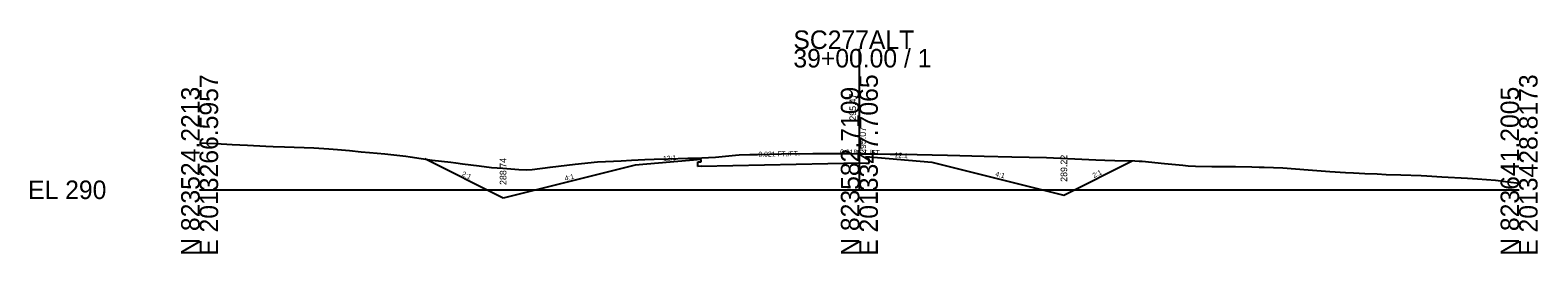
# Model space of a CAD drawing. Extents: x 205929 to 2357175, y -1785700 to 827636.
# Drawn here: x 2018394.5 to 2018623, y 827034.6 to 827068.4 of the extents above; entities that cross this region are included whole.
import ezdxf

# ---------------------------------------------------------------- set-up
doc = ezdxf.new("R2010")
doc.units = 0
for name, color, linetype in [('RD_GPK_XS_Cell', 7, 'Continuous'), ('RD_XS_Base', 7, 'Continuous'), ('RD_XS_EarthShd', 7, 'Continuous'), ('RD_XS_ExGround', 7, 'Continuous'), ('RD_XS_Pave', 7, 'Continuous'), ('RD_XS_TieSlope', 7, 'Continuous'), ('RD_XS_TX_Elev_EX', 7, 'Continuous'), ('RD_XS_TX_Elev_PR', 7, 'Continuous'), ('RD_XS_TX_ShdSlope', 7, 'Continuous'), ('RD_XS_TX_Slope', 7, 'Continuous')]:
    doc.layers.add(name, color=color, linetype=linetype)

msp = doc.modelspace()

# ---------------------------------------------------------------- linework, layer by layer
at = {"layer": 'RD_GPK_XS_Cell'}
for p, q in [((2018520.17, 827044.26), (2018520.17, 827065.59)), ((2018420.17, 827044.26), (2018520.17, 827044.26)), ((2018520.17, 827044.26), (2018620.17, 827044.26))]:
    msp.add_line(p, q, dxfattribs=at)
at = {"layer": 'RD_XS_Base'}
for p, q in [((2018496.17, 827047.83), (2018520.17, 827048.32)), ((2018520.17, 827048.32), (2018521.17, 827048.31))]:
    msp.add_line(p, q, dxfattribs=at)
at = {"layer": 'RD_XS_EarthShd'}
for p, q in [((2018496.17, 827048.83), (2018486.17, 827047.99)), ((2018521.17, 827049.31), (2018531.17, 827048.47))]:
    msp.add_line(p, q, dxfattribs=at)
at = {"layer": 'RD_XS_ExGround'}
msp.add_lwpolyline([(2018420.17, 827051.37), (2018422.63, 827051.25), (2018425.12, 827051.12), (2018427.42, 827051), (2018430.19, 827050.85), (2018431.31, 827050.81), (2018433.04, 827050.79), (2018437.49, 827050.62), (2018439.76, 827050.47), (2018441.07, 827050.36), (2018442.89, 827050.19), (2018444.65, 827050.03), (2018445.92, 827049.92), (2018448.23, 827049.72), (2018451.44, 827049.33), (2018452.09, 827049.25), (2018455.4, 827048.77), (2018458.25, 827048.42), (2018458.98, 827048.33), (2018459.99, 827048.2), (2018462.56, 827047.9), (2018464.41, 827047.66), (2018466.14, 827047.52), (2018468.54, 827047.34), (2018469.72, 827047.27), (2018470.58, 827047.32), (2018473.31, 827047.7), (2018477.09, 827048.14), (2018480.47, 827048.48), (2018482.91, 827048.61), (2018484.05, 827048.66), (2018485.64, 827048.73), (2018487.63, 827048.87), (2018489.07, 827048.9), (2018491.21, 827048.97), (2018494.18, 827049.04), (2018494.79, 827049.05), (2018495.24, 827049.07), (2018498.38, 827049.21), (2018501.4, 827049.5), (2018501.96, 827049.55), (2018503.59, 827049.6), (2018504.75, 827049.62), (2018508.38, 827049.71), (2018513.1, 827049.76), (2018515.43, 827049.78), (2018518.99, 827049.74), (2018520.17, 827049.73), (2018522.92, 827049.7), (2018524.86, 827049.68), (2018526.61, 827049.67), (2018533.54, 827049.49), (2018539.08, 827049.36), (2018543.29, 827049.26), (2018548.53, 827049.13), (2018556, 827048.81), (2018557.38, 827048.75), (2018558.91, 827048.71), (2018561.93, 827048.63), (2018562.59, 827048.61), (2018563.04, 827048.59), (2018566.43, 827048.24), (2018569.21, 827047.97), (2018570.01, 827047.91), (2018571.12, 827047.86), (2018573.59, 827047.77), (2018575.37, 827047.77), (2018577.17, 827047.78), (2018579.67, 827047.73), (2018580.75, 827047.71), (2018581.54, 827047.71), (2018584.34, 827047.6), (2018588.22, 827047.28), (2018591.5, 827047.05), (2018593.87, 827046.88), (2018595.08, 827046.83), (2018596.77, 827046.74), (2018598.66, 827046.66), (2018600.03, 827046.6), (2018602.24, 827046.51), (2018605.31, 827046.41), (2018606.2, 827046.37), (2018608.47, 827046.24), (2018612.36, 827046.02), (2018613.86, 827045.93), (2018616.57, 827045.7), (2018618.52, 827045.47), (2018620.17, 827045.27)], dxfattribs=at)
at = {"layer": 'RD_XS_Pave'}
for p, q in [((2018495.67, 827048.48), (2018496.17, 827048.5)), ((2018495.67, 827047.81), (2018495.67, 827048.48)), ((2018496.17, 827048.5), (2018496.17, 827048.83)), ((2018521.17, 827048.98), (2018521.17, 827049.31)), ((2018521.67, 827048.97), (2018521.17, 827048.98)), ((2018521.17, 827048.31), (2018521.67, 827048.3)), ((2018521.67, 827048.3), (2018521.67, 827048.97)), ((2018496.17, 827047.83), (2018495.67, 827047.81))]:
    msp.add_line(p, q, dxfattribs=at)
at = {"layer": 'RD_XS_TieSlope'}
for p, q in [((2018466.17, 827042.99), (2018454.3, 827048.93)), ((2018531.17, 827048.47), (2018551.17, 827043.47)), ((2018551.17, 827043.47), (2018561.51, 827048.64)), ((2018486.17, 827047.99), (2018466.17, 827042.99))]:
    msp.add_line(p, q, dxfattribs=at)

# ---------------------------------------------------------------- texts
at = {"layer": 'RD_GPK_XS_Cell'}
for s, p in [('SC277ALT', (2018510.17, 827065.59)), ('39+00.00 / 1', (2018510.17, 827062.79)), ('EL 290', (2018394.17, 827042.86))]:
    msp.add_text(s, height=2.8, dxfattribs=at).set_placement(p)
for s, p in [('N 823524.2213', (2018420.17, 827034.26)), ('E 2013266.5957', (2018422.97, 827034.26)), ('N 823582.7109', (2018520.17, 827034.26)), ('E 2013347.7065', (2018522.97, 827034.26)), ('N 823641.2005', (2018620.17, 827034.26)), ('E 2013428.8173', (2018622.97, 827034.26))]:
    msp.add_text(s, height=2.8, rotation=90, dxfattribs=at).set_placement(p)
at = {"layer": 'RD_XS_TX_Elev_EX'}
msp.add_text('295.47', height=1, rotation=90, dxfattribs=at).set_placement((2018519.67, 827054.73))
at = {"layer": 'RD_XS_TX_Elev_PR'}
for s, p in [(' 295.07', (2018521.17, 827049.32)), ('288.74', (2018466.67, 827044.99)), ('289.22', (2018551.67, 827045.47))]:
    msp.add_text(s, height=1, rotation=90, dxfattribs=at).set_placement(p)
at = {"layer": 'RD_XS_TX_ShdSlope'}
for rotation, p in [(4.7636, (2018490.44, 827048.6)), (355.2364, (2018525.48, 827049.2))]:
    msp.add_text('12:1', height=0.75, rotation=rotation, dxfattribs=at).set_placement(p)
at = {"layer": 'RD_XS_TX_Slope'}
for s, rotation, p in [('0.018 FT./FT.', 358.9667, (2018517.25, 827049.63)), ('0.021 FT./FT.', 1.1916, (2018504.88, 827049.26)), ('2:1', 333.4349, (2018459.84, 827046.44)), ('4:1', 14.0362, (2018475.6, 827045.61)), ('4:1', 345.9638, (2018540.72, 827046.34)), ('2:1', 26.5651, (2018555.73, 827046.03))]:
    msp.add_text(s, height=0.75, rotation=rotation, dxfattribs=at).set_placement(p)

doc.saveas('drawing.dxf')
